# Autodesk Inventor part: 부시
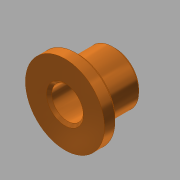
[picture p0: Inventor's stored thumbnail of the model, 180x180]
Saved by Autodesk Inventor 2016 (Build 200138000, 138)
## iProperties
Created: 2016-02
Part Number: 부시
Material: 스테인리스강
Document SubType Name: Modeling
Designer: mduedu
Density: 8.08 g/cm^3
Appearance: 금속 1600F 열
Mass: 45.9536 g
Surface Area: 31.3929 cm^2
Volume: 5.68733 cm^3
Author: mduedu
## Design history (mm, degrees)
sketch "스케치1"
  geometry: C1 r 15 at (0, 0); 1 further point
  constraints: 1 centre point, 1 coincident
  dimensions: "d0" = 30 diameter of C1
extrude "돌출1" new body sketch "스케치1" distance "d1" = 5; taper "d2" = 0 deg
sketch "스케치2"
  geometry: C1 r 10 at (0, 0); 1 further point
  constraints: 1 centre point, 1 coincident
  dimensions: "d3" = 20 diameter of C1
extrude "돌출2" join sketch "스케치2" distance "d4" = 14; taper "d5" = 0 deg
hole "구멍1" diameter "d8" = 12; stored, may be unused: countersink angle "d12" = 90 deg, drill point angle "d14" = 118 deg; dims "d9" = 6, "d10" = 4, "d11" = 2, "d13" = 8, "d15" = 10, "d16" = 10
chamfer "모따기1" distance "d17" = 1; stored, may be unused: second distance "d18" = 2, angle "d19" = 45 deg
chamfer "모따기2" distance "d20" = 1; stored, may be unused: second distance "d21" = 2, angle "d22" = 45 deg
chamfer "모따기3" distance "d23" = 1; stored, may be unused: second distance "d24" = 2, angle "d25" = 45 deg
node "솔리드1"
